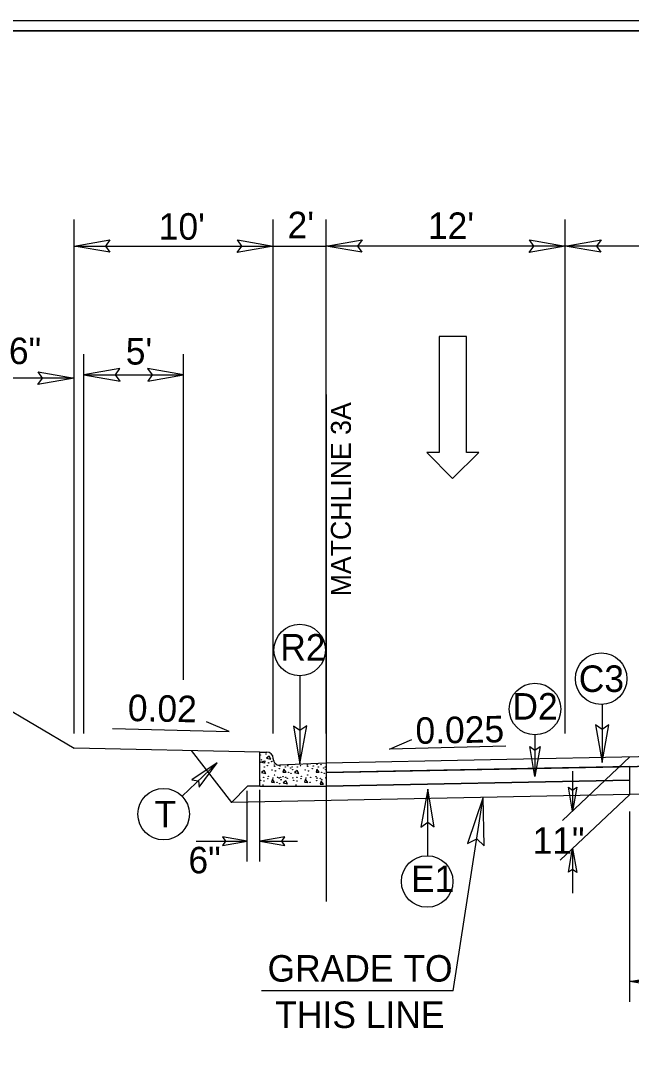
# Model space of a CAD drawing. Extents: x 2320980 to 2456309, y 595047 to 606177.
# Drawn here: x 2455833 to 2455863.6, y 596904 to 596956.6 of the extents above; entities that cross this region are included whole.
import ezdxf

# ---------------------------------------------------------------- set-up
doc = ezdxf.new("R2010")
doc.units = 0
for name, color, linetype in [('Default', 7, 'Continuous'), ('Matchline', 7, 'Continuous'), ('Matchline Text', 7, 'Continuous'), ('Old_Level_1', 7, 'Continuous'), ('Old_Level_11', 7, 'Continuous'), ('Old_Level_20', 7, 'Continuous'), ('Old_Level_21', 7, 'Continuous'), ('Old_Level_3', 7, 'Continuous'), ('Prop Dimension', 7, 'Continuous'), ('Prop Dimension Text', 7, 'Continuous'), ('Prop Lane Arrow CELL', 7, 'Continuous'), ('Prop Terminator CELL', 7, 'Continuous'), ('Sheet Plan CELL', 7, 'Continuous'), ('Sheet Plot Border Inside CELL', 7, 'Continuous'), ('Typical Berm CELL', 7, 'Continuous'), ('Typical Curb CELL', 7, 'Continuous'), ('Typical ID Circle CELL', 7, 'Continuous'), ('Typical Pavement Slope CELL', 7, 'Continuous'), ('Typical Pavement Slope Information CELL', 7, 'Continuous'), ('Typical Terminator CELL', 7, 'Continuous')]:
    doc.layers.add(name, color=color, linetype=linetype)

msp = doc.modelspace()

# ---------------------------------------------------------------- linework, layer by layer
at = {"layer": 'Matchline'}
msp.add_line((2455848.308, 596937.837), (2455848.308, 596912.397), dxfattribs=at)
at = {"layer": 'Old_Level_1'}
for p, q in [((2455863.558, 596917.767), (2455863.558, 596919.161)), ((2455872.308, 596917.942), (2455863.558, 596917.767))]:
    msp.add_line(p, q, dxfattribs=at)
at = {"layer": 'Old_Level_11'}
msp.add_lwpolyline([(2455856.233, 596915.191), (2455856.194, 596917.62), (2455855.402, 596915.307), (2455855.87, 596915.543)], close=True, dxfattribs=at)
at = {"layer": 'Old_Level_21'}
for p, q in [((2455835.648, 596920.818), (2455835.648, 596946.606)), ((2455845.648, 596936.899), (2455845.648, 596946.606)), ((2455848.308, 596920.818), (2455848.308, 596946.606)), ((2455860.308, 596920.818), (2455860.308, 596946.606)), ((2455835.648, 596945.276), (2455848.308, 596945.276)), ((2455873.748, 596945.276), (2455848.308, 596945.276)), ((2455836.148, 596920.818), (2455836.148, 596939.861)), ((2455841.148, 596923.508), (2455841.148, 596939.861)), ((2455835.648, 596938.655), (2455832.236, 596938.655)), ((2455836.148, 596938.818), (2455841.148, 596938.818)), ((2455845.648, 596920.818), (2455845.648, 596936.899)), ((2455820.854, 596928.846), (2455835.648, 596920.084)), ((2455844.35, 596914.405), (2455844.35, 596917.948)), ((2455844.983, 596914.405), (2455844.983, 596917.995)), ((2455854.68, 596907.906), (2455856.194, 596917.62)), ((2455863.558, 596907.35), (2455863.558, 596916.902)), ((2455902.743, 596908.383), (2455863.558, 596908.383)), ((2455854.68, 596907.906), (2455845.06, 596907.906))]:
    msp.add_line(p, q, dxfattribs=at)
at = {"layer": 'Old_Level_3'}
for p, q in [((2455872.308, 596919.334), (2455848.308, 596918.86)), ((2455863.558, 596918.482), (2455848.308, 596918.181))]:
    msp.add_line(p, q, dxfattribs=at)
at = {"layer": 'Prop Dimension'}
for p, q in [((2455863.557, 596919.643), (2455860.179, 596916.46)), ((2455860.68, 596918.931), (2455860.68, 596916.932)), ((2455863.558, 596917.767), (2455860.053, 596914.464)), ((2455860.681, 596915.056), (2455860.681, 596912.804))]:
    msp.add_line(p, q, dxfattribs=at)
at = {"layer": 'Prop Dimension Text'}
for p, q in [((2455858.792, 596920.755), (2455858.792, 596918.672)), ((2455841.082, 596917.67), (2455842.841, 596919.351)), ((2455841.788, 596915.417), (2455844.35, 596915.417)), ((2455844.983, 596915.417), (2455846.87, 596915.417))]:
    msp.add_line(p, q, dxfattribs=at)
for points in [[(2455837.585, 596921.076), (2455843.441, 596920.915), (2455842.304, 596921.403)], [(2455857.336, 596920.192), (2455851.48, 596920.031), (2455852.617, 596920.519)]]:
    msp.add_lwpolyline(points, dxfattribs=at)
for centre in [(2455846.982, 596925.012), (2455862.115, 596923.572), (2455858.793, 596922.048), (2455840.148, 596916.777), (2455853.38, 596913.397)]:
    msp.add_circle(centre, 1.293, dxfattribs=at)
at = {"layer": 'Prop Lane Arrow CELL'}
for p, q in [((2455853.985, 596940.738), (2455853.985, 596934.919)), ((2455855.356, 596940.738), (2455853.985, 596940.738)), ((2455855.356, 596934.919), (2455855.356, 596940.738)), ((2455853.985, 596934.919), (2455853.361, 596934.919)), ((2455853.361, 596934.919), (2455854.65, 596933.61)), ((2455854.65, 596933.61), (2455855.98, 596934.919)), ((2455855.98, 596934.919), (2455855.356, 596934.919))]:
    msp.add_line(p, q, dxfattribs=at)
at = {"layer": 'Prop Terminator CELL'}
for points in [[(2455860.886, 596918.129), (2455860.68, 596916.932), (2455860.467, 596918.135), (2455860.68, 596917.982)], [(2455860.475, 596913.859), (2455860.681, 596915.056), (2455860.894, 596913.852), (2455860.681, 596914.005)]]:
    msp.add_lwpolyline(points, close=True, dxfattribs=at)
at = {"layer": 'Sheet Plan CELL'}
for points in [[(2455742.104, 596746.076), (2455742.099, 596956.071), (2456002.097, 596956.079), (2456002.099, 596926.066), (2456042.107, 596926.064), (2456042.107, 596746.076)], [(2456042.112, 596956.076), (2455742.104, 596956.076), (2455742.104, 596746.076), (2456042.107, 596746.076)]]:
    msp.add_lwpolyline(points, close=True, dxfattribs=at)
at = {"layer": 'Sheet Plot Border Inside CELL'}
msp.add_lwpolyline([(2455711.407, 596745.574), (2456044.604, 596745.576), (2456044.607, 596956.574), (2455711.407, 596956.574)], close=True, dxfattribs=at)
at = {"layer": 'Typical Berm CELL'}
for p, q in [((2455844.983, 596919.889), (2455835.648, 596920.084)), ((2455844.983, 596918.172), (2455844.36, 596918.172))]:
    msp.add_line(p, q, dxfattribs=at)
at = {"layer": 'Typical Curb CELL'}
for p, q in [((2455844.983, 596918.172), (2455844.983, 596919.889)), ((2455844.983, 596919.889), (2455845.329, 596919.889)), ((2455845.032, 596919.386), (2455845.237, 596919.446)), ((2455845.237, 596919.446), (2455845.214, 596919.325)), ((2455845.451, 596919.689), (2455845.314, 596919.589)), ((2455845.314, 596919.589), (2455845.534, 596919.537)), ((2455845.534, 596919.537), (2455845.451, 596919.689)), ((2455845.648, 596919.556), (2455845.648, 596919.57)), ((2455845.214, 596919.325), (2455845.032, 596919.386)), ((2455845.199, 596918.962), (2455845.062, 596918.863)), ((2455845.282, 596918.81), (2455845.199, 596918.962)), ((2455848.308, 596919.335), (2455845.98, 596919.238)), ((2455846.185, 596919.037), (2455846.14, 596918.886)), ((2455846.14, 596918.886), (2455846.299, 596918.878)), ((2455846.299, 596918.878), (2455846.185, 596919.037)), ((2455846.86, 596918.962), (2455846.723, 596918.863)), ((2455846.943, 596918.81), (2455846.86, 596918.962)), ((2455847.846, 596919.037), (2455847.801, 596918.886)), ((2455847.801, 596918.886), (2455847.961, 596918.878)), ((2455847.961, 596918.878), (2455847.846, 596919.037)), ((2455845.062, 596918.863), (2455845.282, 596918.81)), ((2455845.608, 596918.528), (2455845.562, 596918.377)), ((2455845.562, 596918.377), (2455845.721, 596918.368)), ((2455845.721, 596918.368), (2455845.608, 596918.528)), ((2455846.282, 596918.453), (2455846.145, 596918.353)), ((2455846.365, 596918.301), (2455846.282, 596918.453)), ((2455846.723, 596918.863), (2455846.943, 596918.81)), ((2455847.269, 596918.528), (2455847.223, 596918.377)), ((2455847.223, 596918.377), (2455847.384, 596918.368)), ((2455847.384, 596918.368), (2455847.269, 596918.528)), ((2455848.058, 596918.436), (2455848.012, 596918.285)), ((2455848.173, 596918.277), (2455848.058, 596918.436)), ((2455844.983, 596918.172), (2455848.308, 596918.172)), ((2455846.145, 596918.353), (2455846.365, 596918.301)), ((2455848.012, 596918.285), (2455848.173, 596918.277))]:
    msp.add_line(p, q, dxfattribs=at)
for centre in [(2455845.001, 596919.743), (2455845.069, 596919.5), (2455845.289, 596919.788), (2455845.575, 596919.415), (2455845.198, 596919.136), (2455845.358, 596919.204), (2455845.416, 596919.348), (2455845.593, 596918.985), (2455845.7, 596919.242), (2455845.722, 596919.175), (2455845.76, 596918.947), (2455845.958, 596919.061), (2455845.996, 596919.196), (2455846.254, 596919.144), (2455846.383, 596919.201), (2455846.421, 596918.878), (2455846.527, 596919.091), (2455846.602, 596919.136), (2455846.624, 596919.007), (2455846.86, 596919.136), (2455847.019, 596919.204), (2455847.254, 596918.985), (2455847.361, 596919.242), (2455847.384, 596919.175), (2455847.421, 596918.947), (2455847.619, 596919.061), (2455847.657, 596919.196), (2455847.854, 596919.279), (2455847.915, 596919.144), (2455848.044, 596919.257), (2455848.082, 596918.878), (2455848.188, 596919.091), (2455848.263, 596919.136), (2455848.286, 596919.007), (2455845.015, 596918.475), (2455845.176, 596918.62), (2455845.182, 596918.437), (2455845.38, 596918.551), (2455845.403, 596918.673), (2455845.639, 596918.59), (2455845.715, 596918.742), (2455845.843, 596918.369), (2455845.867, 596918.628), (2455845.949, 596918.582), (2455846.024, 596918.627), (2455846.047, 596918.498), (2455846.14, 596918.658), (2455846.282, 596918.627), (2455846.352, 596918.567), (2455846.548, 596918.818), (2455846.632, 596918.597), (2455846.677, 596918.475), (2455846.837, 596918.62), (2455846.844, 596918.437), (2455847.041, 596918.551), (2455847.065, 596918.673), (2455847.3, 596918.59), (2455847.376, 596918.742), (2455847.504, 596918.369), (2455847.528, 596918.628), (2455847.801, 596918.658), (2455847.831, 596918.46), (2455847.854, 596918.582), (2455848.014, 596918.567), (2455848.089, 596918.498), (2455848.21, 596918.818), (2455848.293, 596918.597), (2455845.137, 596918.232), (2455845.971, 596918.308), (2455846.798, 596918.232)]:
    msp.add_circle(centre, 0.0107, dxfattribs=at)
for centre, start, end in [((2455845.329, 596919.57), 0, 90), ((2455845.967, 596919.556), 180, 272.3845)]:
    msp.add_arc(centre, 0.319, start, end, dxfattribs=at)
at = {"layer": 'Typical ID Circle CELL'}
for p, q in [((2455846.993, 596923.719), (2455846.993, 596919.302)), ((2455862.166, 596922.299), (2455862.166, 596919.359)), ((2455853.406, 596914.695), (2455853.406, 596918.033))]:
    msp.add_line(p, q, dxfattribs=at)
at = {"layer": 'Typical Pavement Slope CELL'}
for p, q in [((2455841.525, 596919.961), (2455843.551, 596917.364)), ((2455872.308, 596919.817), (2455848.308, 596919.335)), ((2455872.308, 596919.817), (2455848.308, 596919.335)), ((2455848.308, 596919.335), (2455848.308, 596918.86)), ((2455848.308, 596918.86), (2455872.308, 596919.334)), ((2455863.558, 596919.161), (2455848.308, 596918.86)), ((2455859.265, 596919.077), (2455848.308, 596918.86)), ((2455863.558, 596919.161), (2455859.363, 596919.078)), ((2455863.558, 596918.482), (2455863.558, 596919.161)), ((2455848.308, 596918.86), (2455848.308, 596918.181)), ((2455848.308, 596918.86), (2455848.308, 596918.181)), ((2455848.308, 596918.181), (2455863.558, 596918.482)), ((2455848.308, 596918.181), (2455863.558, 596918.482)), ((2455844.36, 596918.172), (2455843.551, 596917.364)), ((2455863.558, 596917.767), (2455843.555, 596917.367))]:
    msp.add_line(p, q, dxfattribs=at)
msp.add_lwpolyline([(2455859.363, 596919.078), (2455859.265, 596919.077)], dxfattribs=at)
at = {"layer": 'Typical Terminator CELL'}
for points in [[(2455837.443, 596944.967), (2455835.648, 596945.276), (2455837.453, 596945.595), (2455837.224, 596945.276)], [(2455843.852, 596945.585), (2455845.648, 596945.276), (2455843.842, 596944.957), (2455844.072, 596945.276)], [(2455850.103, 596944.967), (2455848.308, 596945.276), (2455850.113, 596945.595), (2455849.884, 596945.276)], [(2455858.512, 596945.585), (2455860.308, 596945.276), (2455858.502, 596944.957), (2455858.732, 596945.276)], [(2455862.103, 596944.967), (2455860.308, 596945.276), (2455862.113, 596945.595), (2455861.884, 596945.276)], [(2455833.848, 596938.965), (2455835.648, 596938.655), (2455833.838, 596938.335), (2455834.068, 596938.655)], [(2455837.948, 596939.128), (2455836.148, 596938.818), (2455837.958, 596938.498), (2455837.728, 596938.818)], [(2455839.348, 596938.508), (2455841.148, 596938.818), (2455839.338, 596939.138), (2455839.568, 596938.818)], [(2455846.667, 596921.197), (2455846.993, 596919.302), (2455847.33, 596921.207), (2455846.993, 596920.965)], [(2455861.839, 596921.254), (2455862.166, 596919.359), (2455862.503, 596921.264), (2455862.166, 596921.022)], [(2455859.05, 596920.169), (2455858.792, 596918.672), (2455858.526, 596920.177), (2455858.792, 596919.986)], [(2455841.938, 596918.131), (2455842.841, 596919.351), (2455841.57, 596918.504), (2455841.892, 596918.443)], [(2455853.732, 596916.138), (2455853.406, 596918.033), (2455853.069, 596916.127), (2455853.406, 596916.37)], [(2455843.103, 596915.202), (2455844.35, 596915.417), (2455843.096, 596915.639), (2455843.256, 596915.417)], [(2455846.23, 596915.632), (2455844.983, 596915.417), (2455846.237, 596915.195), (2455846.077, 596915.417)], [(2455865.354, 596908.074), (2455863.558, 596908.383), (2455865.364, 596908.702), (2455865.134, 596908.383)]]:
    msp.add_lwpolyline(points, close=True, dxfattribs=at)

# ---------------------------------------------------------------- texts
at = {"layer": 'Default'}
for s, rotation, p in [('6"', 0.0002, (2455832.379, 596939.356)), ("5'", 359.9998, (2455838.245, 596939.333))]:
    msp.add_text(s, height=1.33, rotation=rotation, dxfattribs=at).set_placement(p)
at = {"layer": 'Matchline Text'}
msp.add_text('MATCHLINE 3A', height=1, rotation=90, dxfattribs=at).set_placement((2455849.549, 596927.707))
at = {"layer": 'Old_Level_20'}
for s, p in [('R2', (2455846.004, 596924.482)), ('C3', (2455860.991, 596922.907)), ('T', (2455839.686, 596916.112)), ('E1', (2455852.569, 596912.868))]:
    msp.add_text(s, height=1.33, dxfattribs=at).set_placement(p)
msp.add_text('D2', height=1.33, rotation=359.9972, dxfattribs=at).set_placement((2455857.659, 596921.519))
at = {"layer": 'Old_Level_21'}
for s, p in [("10'", (2455839.903, 596945.599)), ("12'", (2455853.417, 596945.635)), ('6"', (2455841.393, 596913.806)), ('GRADE TO', (2455845.366, 596908.372)), ('THIS LINE', (2455845.753, 596906.045))]:
    msp.add_text(s, height=1.33, dxfattribs=at).set_placement(p)
for s, rotation, p in [("2'", 359.9998, (2455846.371, 596945.672)), ('0.02', 358.8544, (2455838.341, 596921.448)), ('0.025', 1.1456, (2455852.805, 596920.297))]:
    msp.add_text(s, height=1.33, rotation=rotation, dxfattribs=at).set_placement(p)
at = {"layer": 'Typical Pavement Slope Information CELL'}
msp.add_text('11"', height=1.33, dxfattribs=at).set_placement((2455858.67, 596914.789))

doc.saveas('drawing.dxf')
